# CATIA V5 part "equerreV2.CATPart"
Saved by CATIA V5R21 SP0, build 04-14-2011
Part number: equerre
Bounding box of the stored display mesh (mm): x -0.995 to 17.005, y -11.441 to 6.559, z -15 to 3
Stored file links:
  C:\Users\2027.DESARCY-LEMIE30\Desktop\V14(17.02.2023)\equerreV2.CATPart
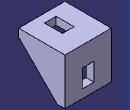
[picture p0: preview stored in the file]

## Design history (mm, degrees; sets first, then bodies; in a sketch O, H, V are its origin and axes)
Body1 (main body)
  Sketch1 on xy-plane, origin (0, 0, 0), H (1, 0, 0), V (0, 1, 0)
    line L1 (-0.9951, 6.5593) -> (17.0049, 6.5593)
    line L2 (17.0049, 6.5593) -> (17.0049, -11.4407)
    line L3 (17.0049, -11.4407) -> (-0.9951, -11.4407)
    line L4 (-0.9951, -11.4407) -> (-0.9951, 6.5593)
    length L2 = 18
    length L1 = 18
    horizontal: L1 H, L3 H
    vertical: L2 V, L4 V
  Pad1: profile Sketch1, direction (0, 0, 1), length 3
  Sketch2 on start face of Pad1, origin (0, 0, 0), H (1, 0, 0), V (0, -1, 0)
    point P1 (17.0049, -3.5593)
    reference projected line E1 (17.0049, 11.4407) -> (17.0049, -6.5593) from edge [start face of Pad1 | face of Pad1 from Sketch1.L2]
    reference projected point E2 (17.0049, -6.5593) from vertex [face of Pad1 from Sketch1.L1 | start face of Pad1 | face of Pad1 from Sketch1.L2]
    line L1 (17.0049, -3.5593) -> (17.0049, -6.5593)
    line L2 (17.0049, -3.5593) -> (-0.9951, -3.5593)
    line L3 (17.0049, -6.5593) -> (-0.9951, -6.5593)
    line L4 (-0.9951, -3.5593) -> (-0.9951, -6.5593)
    distance P1 E2 = 3
    length L2 = 18
    coincidence: P1 E1
    vertical: L1 V, L4 V
    horizontal: L2 H, L3 H
  Pad2: profile Sketch2, direction (0, 0, -1), length 15
  Sketch3 on face of Pad2, origin (17.0049, 0, 0), H (0, 1, 0), V (0, 0, 1)
    point P1 (3.5593, -15)
    point P2 (3.5593, 0)
    point P3 (-11.4407, 0)
    reference projected point E1 (-11.4407, 0) from vertex [face of Pad1 from Sketch1.L2 | start face of Pad1 | face of Pad1 from Sketch1.L3]
    reference projected point E2 (3.5593, 0) from vertex [start face of Pad1 | face of Pad2 | face of Pad2 from Sketch2.L2]
    reference projected point E3 (3.5593, -15) from vertex [face of Pad2 from Sketch2.L1 | end face of Pad2 | face of Pad2 from Sketch2.L2]
    line L1 (-11.4407, 0) -> (3.5593, 0)
    line L2 (3.5593, 0) -> (3.5593, -15)
    line L3 (-11.4407, 0) -> (3.5593, -15)
    coincidence: E1 P3, E2 P2, P1 E3
    horizontal: L1 H
    vertical: L2 V
  Pad3: profile Sketch3, direction (-1, 0, 0), length 3
  Sketch4 on face of Pad2, origin (-0.9951, 0, 0), H (0, -1, 0), V (0, 0, 1)
    point P1 (-3.5593, 0)
    point P2 (11.4407, 0)
    point P3 (-3.5593, -15)
    reference projected point E1 (-3.5593, 0) from vertex [start face of Pad1 | face of Pad2 | face of Pad2 from Sketch2.L2]
    reference projected point E2 (11.4407, 0) from vertex [face of Pad1 from Sketch1.L3 | start face of Pad1 | face of Pad1 from Sketch1.L4]
    reference projected point E3 (-3.5593, -15) from vertex [face of Pad2 from Sketch2.L4 | end face of Pad2 | face of Pad2 from Sketch2.L2]
    line L1 (-3.5593, 0) -> (11.4407, 0)
    line L2 (11.4407, 0) -> (-3.5593, -15)
    line L3 (-3.5593, 0) -> (-3.5593, -15)
    coincidence: E1 P1, E2 P2, E3 P3
    horizontal: L1 H
    vertical: L3 V
  Pad4: profile Sketch4, direction (1, 0, 0), length 3
  Sketch5 on start face of Pad1, origin (0, 0, 0), H (1, 0, 0), V (0, -1, 0)
    point P1 (10.2549, 8.1407)
    point P2 (5.7549, 8.1407)
    point P3 (10.2549, 1.1407)
    reference projected line E1 (-0.9951, -6.5593) -> (17.0049, -6.5593) from edge [face of Pad2 | end face of Pad2]
    reference projected line E2 (17.0049, 11.4407) -> (17.0049, -3.5593) from edge [face of Pad3 from Sketch3.L3 | face of Pad3]
    reference projected line E3 (-0.9951, -3.5593) -> (-0.9951, 11.4407) from edge [face of Pad4 from Sketch4.L2 | face of Pad4]
    line L1 (5.7549, 8.1407) -> (10.2549, 8.1407)
    line L2 (10.2549, 8.1407) -> (10.2549, 1.1407)
    line L3 (10.2549, 1.1407) -> (5.7549, 1.1407)
    line L4 (5.7549, 1.1407) -> (5.7549, 8.1407)
    distance P1 E1 = 14.7
    distance P1 E2 = 6.75
    distance P2 E3 = 6.75
    distance P3 P1 = 7
    horizontal: L1 H, L3 H
    vertical: L2 V, L4 V
  Pocket1: profile Sketch5, direction (0, 0, 1), length 3
  Sketch6 on face of Pad2 from Sketch2.L2, origin (0, 3.5593, 0), H (1, 0, 0), V (0, 0, 1)
    point P1 (5.7549, -4.7)
    point P2 (10.2549, -4.7)
    point P3 (5.7549, -11.7)
    reference projected line E1 (-0.9951, 3) -> (17.0049, 3) from edge [face of Pad1 from Sketch1.L3 | end face of Pad1]
    reference projected line E2 (17.0049, 0) -> (17.0049, -15) from edge [face of Pad3 from Sketch3.L3 | face of Pad3]
    reference projected line E3 (-0.9951, -15) -> (-0.9951, 0) from edge [face of Pad4 from Sketch4.L2 | face of Pad4]
    line L1 (5.7549, -4.7) -> (10.2549, -4.7)
    line L2 (5.7549, -11.7) -> (10.2549, -11.7)
    line L3 (5.7549, -4.7) -> (5.7549, -11.7)
    line L4 (10.2549, -4.7) -> (10.2549, -11.7)
    distance P3 E1 = 14.7
    distance P2 E2 = 6.75
    distance P1 E3 = 6.75
    distance P1 P3 = 7
    horizontal: L1 H, L2 H
    vertical: L3 V, L4 V
  Pocket2: profile Sketch6, direction (0, 1, 0), length 3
